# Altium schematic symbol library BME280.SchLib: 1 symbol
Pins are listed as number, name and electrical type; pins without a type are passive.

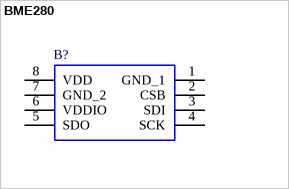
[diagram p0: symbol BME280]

## BME280
designator B?
Board Mount Humidity Sensors; Manufacturer_Name: Bosch Sensortec
footprint BME280
pins: 1 GND_1, 2 CSB, 3 SDI, 4 SCK, 5 SDO, 6 VDDIO (power), 7 GND_2, 8 VDD (power)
